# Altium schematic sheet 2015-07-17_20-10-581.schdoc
size 290 x 170 mm; SheetNumber: 1; SheetTotal: 1
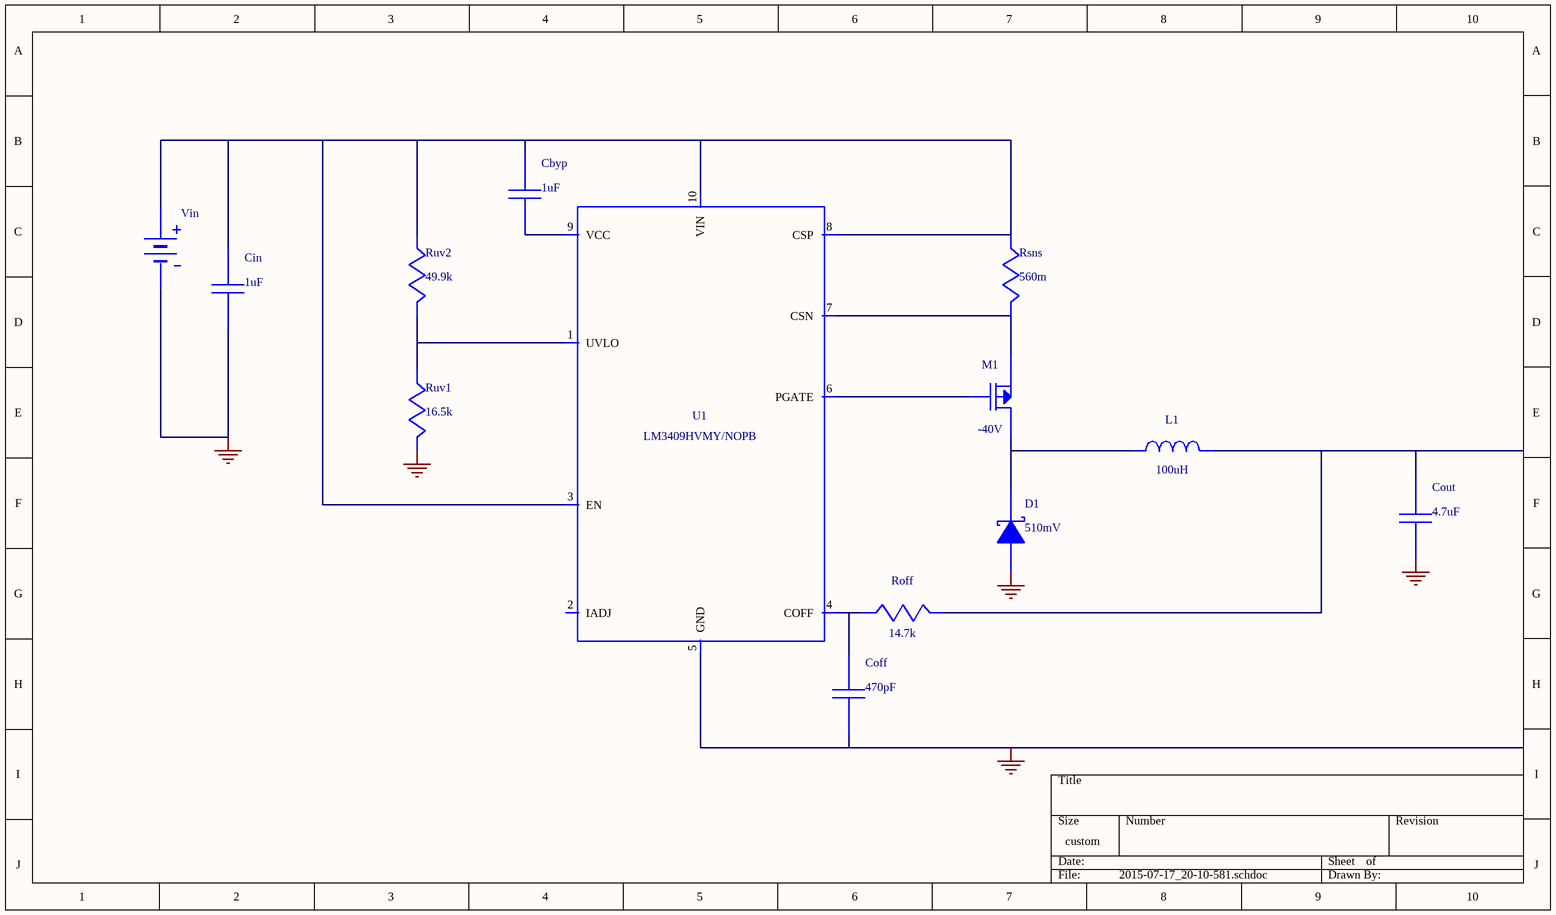
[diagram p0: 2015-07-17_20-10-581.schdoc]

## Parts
Cbyp  value 1uF  (hidden comment: GRM21BR61C105KA01L)
Cin  value 1uF  (hidden comment: C3216X5R1H105K)
Coff  value 470pF  (hidden comment: CC0805KRX7R9BB471)
Cout  value 4.7uF  (hidden comment: GRM31CR71H475KA12L)
D1  value 510mV  (hidden comment: MBR0540T1G)
L1  value 100uH  (hidden comment: SRN6045-101M)
M1  value -40V  (hidden comment: SI2319DS-T1-E3)
Roff  value 14.7k  (hidden comment: CRCW040214K7FKED)
Rsns  value 560m  (hidden comment: ERJ-3RQFR56V)
Ruv1  value 16.5k  (hidden comment: CRCW040216K5FKED)
Ruv2  value 49.9k  (hidden comment: CRCW040249K9FKED)
U1  LM3409HVMY/NOPB
Vin  WB_BATTERY  (value not drawn)

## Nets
0: Cin.2 Coff.2 Cout.2 D1.2(A) Ruv1.1 U1.5(GND) U1.11(DAP) Vin.2(-)
NetCbyp_1: Cbyp.1 Cin.1 Rsns.2 Ruv2.2 U1.3(EN) U1.8(CSP) U1.10(VIN) Vin.1(+)
NetCbyp_2: Cbyp.2 U1.9(VCC)
NetCoff_1: Coff.1 Roff.2 U1.4(COFF)
NetCout_1: Cout.1 L1.2 Roff.1
NetD1_1: D1.1(K) L1.1 M1.3(Drain)
NetM1_1: M1.1(Gate) U1.6(PGATE)
NetM1_2: M1.2(Source) Rsns.1 U1.7(CSN)
NetRuv1_2: Ruv1.2 Ruv2.1 U1.1(UVLO)

Not connected (* = marked no-connect by the designer): U1 2(IADJ)

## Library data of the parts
Cbyp = GRM21BR61C105KA01L: GRM21BR61C105KA0; Manufacturer Name: MuRata
Cin = C3216X5R1H105K: Manufacturer Name: TDK
Coff = CC0805KRX7R9BB471: CC0805KRX7R9BB47; Manufacturer Name: Yageo America
Cout = GRM31CR71H475KA12L: GRM31CR71H475KA1; Manufacturer Name: MuRata
D1 = MBR0540T1G: Manufacturer Name: ON Semiconductor
L1 = SRN6045-101M: Manufacturer Name: Bourns
M1 = SI2319DS-T1-E3: Manufacturer Name: Vishay-Siliconix
Roff = CRCW040214K7FKED: Manufacturer Name: Vishay-Dale
Rsns = ERJ-3RQFR56V: Manufacturer Name: Panasonic
Ruv1 = CRCW040216K5FKED: Manufacturer Name: Vishay-Dale
Ruv2 = CRCW040249K9FKED: Manufacturer Name: Vishay-Dale
U1 = LM3409HVMY/NOPB: Manufacturer Name: Texas Instruments; Value: UNLISTED
Vin = WB_BATTERY: Value: UNLISTED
